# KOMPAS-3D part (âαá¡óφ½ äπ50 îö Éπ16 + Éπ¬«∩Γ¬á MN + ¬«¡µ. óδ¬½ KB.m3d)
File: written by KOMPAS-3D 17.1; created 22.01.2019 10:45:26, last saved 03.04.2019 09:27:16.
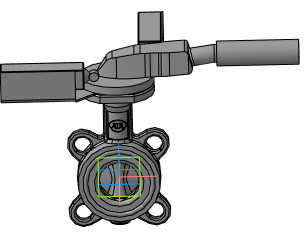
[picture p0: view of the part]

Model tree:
1. Операция без истории:2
